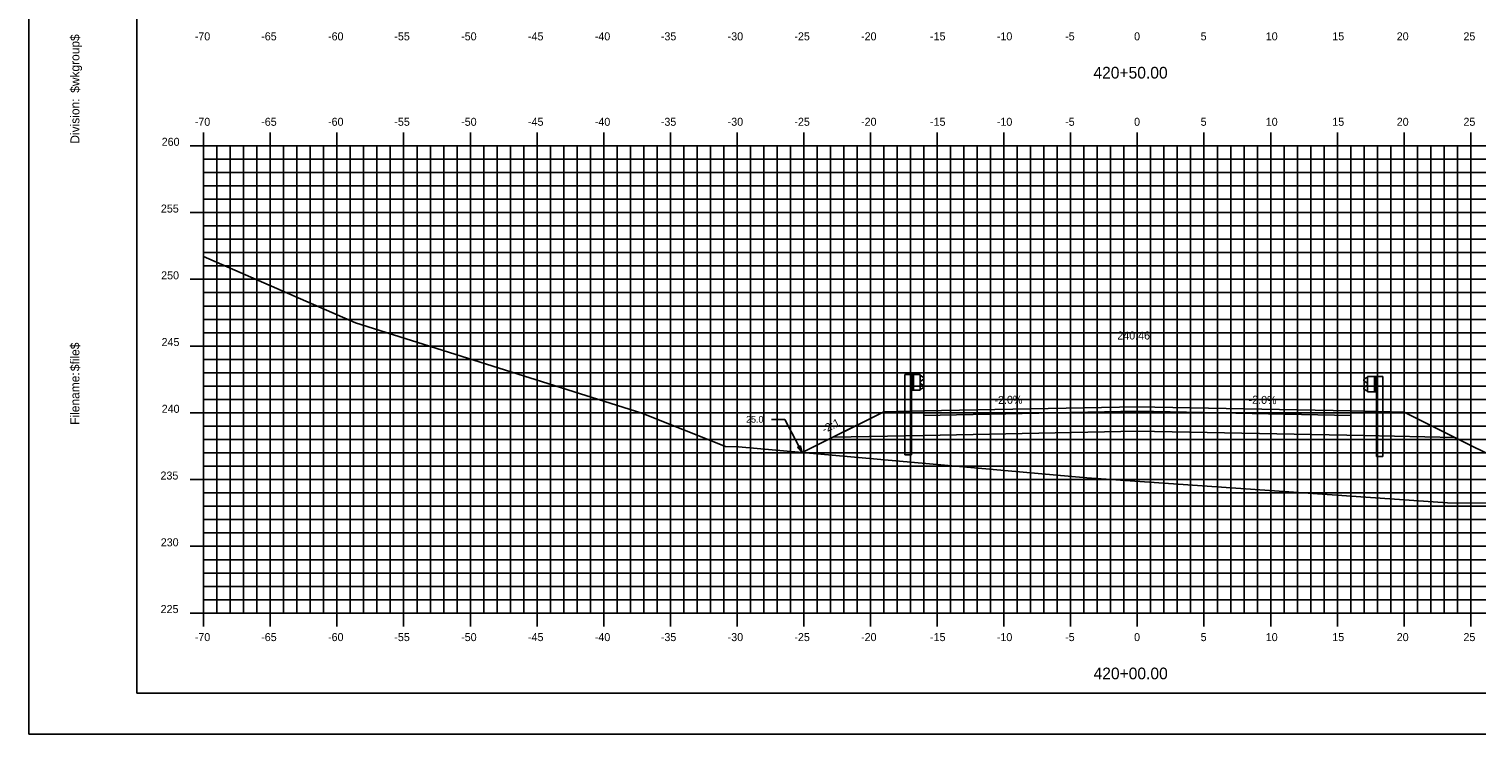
# Model space of a CAD drawing. Extents: x 1160718 to 1173142, y 616002 to 617630.
# Drawn here: x 1169435.8 to 1169544.3, y 616613.9 to 616666.7 of the extents above; entities that cross this region are included whole.
import ezdxf

# ---------------------------------------------------------------- set-up
doc = ezdxf.new("R2010")
doc.units = 0
for name, color, linetype in [('ANNOTATION', 7, 'Continuous'), ('BORDER', 7, 'Continuous'), ('D_Guardrail_Beam_Lt', 7, 'Continuous'), ('D_Guardrail_Beam_Rt', 7, 'Continuous'), ('D_Roadway_Centerline', 7, 'Continuous'), ('D_Roadway_Centerline_Text', 7, 'Continuous'), ('D_Roadway_Edge_Shoulder', 7, 'Continuous'), ('D_Roadway_Edge_TW', 7, 'Continuous'), ('D_Roadway_Pavement', 7, 'Continuous'), ('D_Roadway_SlopeLines', 7, 'Continuous'), ('D_Roadway_SubGrade', 7, 'Continuous'), ('H_V ANNOTATION', 7, 'Continuous'), ('MAJOR', 7, 'Continuous'), ('MINOR', 7, 'Continuous'), ('PLOT BOUNDARY', 7, 'Continuous'), ('S_Roadway_Centerline', 7, 'Continuous')]:
    doc.layers.add(name, color=color, linetype=linetype)

msp = doc.modelspace()

# ---------------------------------------------------------------- linework, layer by layer
at = {"layer": 'ANNOTATION'}
for p in [(1169491.45, 616637.44), (1169493.75, 616634.95)]:
    msp.add_line(p, (1169492.45, 616637.44), dxfattribs=at)
msp.add_lwpolyline([(1169496.06, 616636.1), (1169502.88, 616636.24), (1169518.88, 616636.56), (1169535.88, 616636.22), (1169542.7, 616636.08)], dxfattribs=at)
msp.add_lwpolyline([(1169493.63, 616635.45), (1169493.75, 616634.95), (1169493.41, 616635.33)], close=True, dxfattribs=at)
at = {"layer": 'BORDER'}
for p, q in [((1169443.88, 616721.93), (1169443.88, 616616.93)), ((1169443.88, 616616.93), (1169603.88, 616616.93))]:
    msp.add_line(p, q, dxfattribs=at)
at = {"layer": 'D_Guardrail_Beam_Lt'}
for p, q in [((1169501.45, 616640.79), (1169501.45, 616634.79)), ((1169501.92, 616640.79), (1169501.45, 616640.79)), ((1169502.61, 616640.79), (1169501.92, 616640.79)), ((1169501.92, 616640.79), (1169501.92, 616639.62)), ((1169501.99, 616640.79), (1169501.99, 616639.62)), ((1169502.09, 616640.79), (1169502.09, 616639.62)), ((1169502.61, 616639.62), (1169502.61, 616640.79)), ((1169502.61, 616640.7), (1169502.68, 616640.69)), ((1169502.61, 616640.24), (1169502.61, 616640.17)), ((1169502.84, 616640.44), (1169502.65, 616640.3)), ((1169502.65, 616640.1), (1169502.84, 616639.97)), ((1169502.7, 616640.68), (1169502.84, 616640.58)), ((1169501.92, 616639.62), (1169502.61, 616639.62)), ((1169501.94, 616634.79), (1169501.94, 616639.62)), ((1169502.68, 616639.72), (1169502.61, 616639.7)), ((1169502.84, 616639.82), (1169502.7, 616639.72)), ((1169501.94, 616634.79), (1169501.45, 616634.79))]:
    msp.add_line(p, q, dxfattribs=at)
for centre, major_axis, start_param, end_param in [((1169502.69, 616640.24), (-0.0789, 0), 5.323254, 6.283185), ((1169502.69, 616640.17), (-0.0789, 0), 6.283185, 7.243116), ((1169502.68, 616640.65), (0.0417, 0), 0.959931, 1.376053), ((1169502.79, 616640.51), (0.0877, 0), 5.323254, 7.243116), ((1169502.79, 616639.9), (0.0877, 0), 5.323254, 7.243116), ((1169502.68, 616639.76), (0.0417, 0), 4.907132, 5.323254)]:
    msp.add_ellipse(centre, major_axis=major_axis, ratio=0.995501, start_param=start_param, end_param=end_param, dxfattribs=at)
at = {"layer": 'D_Guardrail_Beam_Rt'}
for p, q in [((1169536.04, 616640.55), (1169535.9, 616640.45)), ((1169535.9, 616640.31), (1169536.09, 616640.17)), ((1169536.09, 616639.97), (1169535.9, 616639.84)), ((1169536.13, 616640.57), (1169536.06, 616640.56)), ((1169536.13, 616640.65), (1169536.82, 616640.65)), ((1169536.13, 616639.49), (1169536.13, 616640.65)), ((1169536.13, 616640.11), (1169536.13, 616640.04)), ((1169536.65, 616640.65), (1169536.65, 616639.49)), ((1169536.76, 616640.65), (1169536.76, 616639.49)), ((1169536.82, 616640.65), (1169537.29, 616640.65)), ((1169536.82, 616640.65), (1169536.82, 616639.49)), ((1169537.29, 616640.65), (1169537.29, 616634.65)), ((1169535.9, 616639.69), (1169536.04, 616639.59)), ((1169536.06, 616639.59), (1169536.13, 616639.57)), ((1169536.82, 616639.49), (1169536.13, 616639.49)), ((1169536.8, 616634.65), (1169536.8, 616639.49)), ((1169536.8, 616634.65), (1169537.29, 616634.65))]:
    msp.add_line(p, q, dxfattribs=at)
for centre, major_axis, start_param, end_param in [((1169535.95, 616640.38), (-0.0877, 0), 5.323254, 7.243116), ((1169536.07, 616640.52), (-0.0417, 0), 4.907132, 5.323254), ((1169536.05, 616640.11), (0.0789, 0), 0, 0.959931), ((1169536.05, 616640.04), (0.0789, 0), 5.323254, 6.283185), ((1169535.95, 616639.76), (-0.0877, 0), 5.323254, 7.243116), ((1169536.07, 616639.63), (-0.0417, 0), 0.959931, 1.376053)]:
    msp.add_ellipse(centre, major_axis=major_axis, ratio=0.995501, start_param=start_param, end_param=end_param, dxfattribs=at)
at = {"layer": 'D_Roadway_Edge_Shoulder'}
for points in [[(1169502.88, 616638.07), (1169502.88, 616637.74)], [(1169534.88, 616638.07), (1169534.88, 616637.74)]]:
    msp.add_lwpolyline(points, dxfattribs=at)
at = {"layer": 'D_Roadway_Edge_TW'}
msp.add_lwpolyline([(1169502.88, 616637.74), (1169502.88, 616638.07), (1169518.88, 616638.39), (1169534.88, 616638.07), (1169534.88, 616637.74), (1169518.88, 616638.06)], close=True, dxfattribs=at)
at = {"layer": 'D_Roadway_Pavement'}
msp.add_lwpolyline([(1169502.88, 616637.74), (1169502.88, 616637.74), (1169518.88, 616638.06), (1169534.88, 616637.74), (1169534.88, 616637.74), (1169518.88, 616638.06)], close=True, dxfattribs=at)
for points in [[(1169502.88, 616637.74), (1169502.88, 616637.74)], [(1169502.88, 616637.74), (1169502.88, 616637.74)], [(1169534.88, 616637.74), (1169534.88, 616637.74)], [(1169534.88, 616637.74), (1169534.88, 616637.74)]]:
    msp.add_lwpolyline(points, dxfattribs=at)
at = {"layer": 'D_Roadway_SlopeLines'}
for points in [[(1169499.88, 616638.01), (1169493.75, 616634.95)], [(1169538.88, 616637.99), (1169549.96, 616632.45)]]:
    msp.add_lwpolyline(points, dxfattribs=at)
at = {"layer": 'D_Roadway_SubGrade'}
for p, q in [((1169534.88, 616638.07), (1169538.88, 616637.99)), ((1169534.88, 616636.24), (1169534.88, 616638.07)), ((1169538.88, 616637.99), (1169543.74, 616635.56))]:
    msp.add_line(p, q, dxfattribs=at)
for points in [[(1169502.88, 616636.24), (1169502.88, 616638.07), (1169499.88, 616638.01), (1169496.06, 616636.1)], [(1169502.88, 616636.24), (1169502.88, 616637.74), (1169518.88, 616638.06), (1169534.88, 616637.74), (1169534.88, 616636.24)]]:
    msp.add_lwpolyline(points, dxfattribs=at)
at = {"layer": 'MAJOR'}
for p, q in [((1169448.88, 616658.93), (1169448.88, 616657.93)), ((1169453.88, 616658.93), (1169453.88, 616657.93)), ((1169458.88, 616658.93), (1169458.88, 616657.93)), ((1169463.88, 616658.93), (1169463.88, 616657.93)), ((1169468.88, 616658.93), (1169468.88, 616657.93)), ((1169473.88, 616658.93), (1169473.88, 616657.93)), ((1169478.88, 616658.93), (1169478.88, 616657.93)), ((1169483.88, 616658.93), (1169483.88, 616657.93)), ((1169488.88, 616658.93), (1169488.88, 616657.93)), ((1169493.88, 616658.93), (1169493.88, 616657.93)), ((1169498.88, 616658.93), (1169498.88, 616657.93)), ((1169503.88, 616658.93), (1169503.88, 616657.93)), ((1169508.88, 616658.93), (1169508.88, 616657.93)), ((1169513.88, 616658.93), (1169513.88, 616657.93)), ((1169518.88, 616658.93), (1169518.88, 616657.93)), ((1169523.88, 616658.93), (1169523.88, 616657.93)), ((1169528.88, 616658.93), (1169528.88, 616657.93)), ((1169533.88, 616658.93), (1169533.88, 616657.93)), ((1169538.88, 616658.93), (1169538.88, 616657.93)), ((1169543.88, 616658.93), (1169543.88, 616657.93)), ((1169447.88, 616657.93), (1169448.88, 616657.93)), ((1169448.88, 616657.93), (1169588.88, 616657.93)), ((1169448.88, 616622.93), (1169448.88, 616657.93)), ((1169448.88, 616622.93), (1169448.88, 616657.93)), ((1169448.88, 616657.93), (1169588.88, 616657.93)), ((1169453.88, 616622.93), (1169453.88, 616657.93)), ((1169458.88, 616622.93), (1169458.88, 616657.93)), ((1169463.88, 616622.93), (1169463.88, 616657.93)), ((1169468.88, 616622.93), (1169468.88, 616657.93)), ((1169473.88, 616622.93), (1169473.88, 616657.93)), ((1169478.88, 616622.93), (1169478.88, 616657.93)), ((1169483.88, 616622.93), (1169483.88, 616657.93)), ((1169488.88, 616622.93), (1169488.88, 616657.93)), ((1169493.88, 616622.93), (1169493.88, 616657.93)), ((1169498.88, 616622.93), (1169498.88, 616657.93)), ((1169503.88, 616622.93), (1169503.88, 616657.93)), ((1169508.88, 616622.93), (1169508.88, 616657.93)), ((1169513.88, 616622.93), (1169513.88, 616657.93)), ((1169518.88, 616622.93), (1169518.88, 616657.93)), ((1169523.88, 616622.93), (1169523.88, 616657.93)), ((1169528.88, 616622.93), (1169528.88, 616657.93)), ((1169533.88, 616622.93), (1169533.88, 616657.93)), ((1169538.88, 616622.93), (1169538.88, 616657.93)), ((1169543.88, 616622.93), (1169543.88, 616657.93)), ((1169447.88, 616652.93), (1169448.88, 616652.93)), ((1169448.88, 616652.93), (1169588.88, 616652.93)), ((1169447.88, 616647.93), (1169448.88, 616647.93)), ((1169448.88, 616647.93), (1169588.88, 616647.93)), ((1169447.88, 616642.93), (1169448.88, 616642.93)), ((1169448.88, 616642.93), (1169588.88, 616642.93)), ((1169447.88, 616637.93), (1169448.88, 616637.93)), ((1169448.88, 616637.93), (1169588.88, 616637.93)), ((1169447.88, 616632.93), (1169448.88, 616632.93)), ((1169448.88, 616632.93), (1169588.88, 616632.93)), ((1169447.88, 616627.93), (1169448.88, 616627.93)), ((1169448.88, 616627.93), (1169588.88, 616627.93)), ((1169447.88, 616622.93), (1169448.88, 616622.93)), ((1169448.88, 616622.93), (1169588.88, 616622.93)), ((1169448.88, 616622.93), (1169588.88, 616622.93)), ((1169448.88, 616621.93), (1169448.88, 616622.93)), ((1169453.88, 616621.93), (1169453.88, 616622.93)), ((1169458.88, 616621.93), (1169458.88, 616622.93)), ((1169463.88, 616621.93), (1169463.88, 616622.93)), ((1169468.88, 616621.93), (1169468.88, 616622.93)), ((1169473.88, 616621.93), (1169473.88, 616622.93)), ((1169478.88, 616621.93), (1169478.88, 616622.93)), ((1169483.88, 616621.93), (1169483.88, 616622.93)), ((1169488.88, 616621.93), (1169488.88, 616622.93)), ((1169493.88, 616621.93), (1169493.88, 616622.93)), ((1169498.88, 616621.93), (1169498.88, 616622.93)), ((1169503.88, 616621.93), (1169503.88, 616622.93)), ((1169508.88, 616621.93), (1169508.88, 616622.93)), ((1169513.88, 616621.93), (1169513.88, 616622.93)), ((1169518.88, 616621.93), (1169518.88, 616622.93)), ((1169523.88, 616621.93), (1169523.88, 616622.93)), ((1169528.88, 616621.93), (1169528.88, 616622.93)), ((1169533.88, 616621.93), (1169533.88, 616622.93)), ((1169538.88, 616621.93), (1169538.88, 616622.93)), ((1169543.88, 616621.93), (1169543.88, 616622.93))]:
    msp.add_line(p, q, dxfattribs=at)
at = {"layer": 'MINOR'}
for p, q in [((1169449.88, 616622.93), (1169449.88, 616657.93)), ((1169450.88, 616622.93), (1169450.88, 616657.93)), ((1169451.88, 616622.93), (1169451.88, 616657.93)), ((1169452.88, 616622.93), (1169452.88, 616657.93)), ((1169454.88, 616622.93), (1169454.88, 616657.93)), ((1169455.88, 616622.93), (1169455.88, 616657.93)), ((1169456.88, 616622.93), (1169456.88, 616657.93)), ((1169457.88, 616622.93), (1169457.88, 616657.93)), ((1169459.88, 616622.93), (1169459.88, 616657.93)), ((1169460.88, 616622.93), (1169460.88, 616657.93)), ((1169461.88, 616622.93), (1169461.88, 616657.93)), ((1169462.88, 616622.93), (1169462.88, 616657.93)), ((1169464.88, 616622.93), (1169464.88, 616657.93)), ((1169465.88, 616622.93), (1169465.88, 616657.93)), ((1169466.88, 616622.93), (1169466.88, 616657.93)), ((1169467.88, 616622.93), (1169467.88, 616657.93)), ((1169469.88, 616622.93), (1169469.88, 616657.93)), ((1169470.88, 616622.93), (1169470.88, 616657.93)), ((1169471.88, 616622.93), (1169471.88, 616657.93)), ((1169472.88, 616622.93), (1169472.88, 616657.93)), ((1169474.88, 616622.93), (1169474.88, 616657.93)), ((1169475.88, 616622.93), (1169475.88, 616657.93)), ((1169476.88, 616622.93), (1169476.88, 616657.93)), ((1169477.88, 616622.93), (1169477.88, 616657.93)), ((1169479.88, 616622.93), (1169479.88, 616657.93)), ((1169480.88, 616622.93), (1169480.88, 616657.93)), ((1169481.88, 616622.93), (1169481.88, 616657.93)), ((1169482.88, 616622.93), (1169482.88, 616657.93)), ((1169484.88, 616622.93), (1169484.88, 616657.93)), ((1169485.88, 616622.93), (1169485.88, 616657.93)), ((1169486.88, 616622.93), (1169486.88, 616657.93)), ((1169487.88, 616622.93), (1169487.88, 616657.93)), ((1169489.88, 616622.93), (1169489.88, 616657.93)), ((1169490.88, 616622.93), (1169490.88, 616657.93)), ((1169491.88, 616622.93), (1169491.88, 616657.93)), ((1169492.88, 616622.93), (1169492.88, 616657.93)), ((1169494.88, 616622.93), (1169494.88, 616657.93)), ((1169495.88, 616622.93), (1169495.88, 616657.93)), ((1169496.88, 616622.93), (1169496.88, 616657.93)), ((1169497.88, 616622.93), (1169497.88, 616657.93)), ((1169499.88, 616622.93), (1169499.88, 616657.93)), ((1169500.88, 616622.93), (1169500.88, 616657.93)), ((1169501.88, 616622.93), (1169501.88, 616657.93)), ((1169502.88, 616622.93), (1169502.88, 616657.93)), ((1169504.88, 616622.93), (1169504.88, 616657.93)), ((1169505.88, 616622.93), (1169505.88, 616657.93)), ((1169506.88, 616622.93), (1169506.88, 616657.93)), ((1169507.88, 616622.93), (1169507.88, 616657.93)), ((1169509.88, 616622.93), (1169509.88, 616657.93)), ((1169510.88, 616622.93), (1169510.88, 616657.93)), ((1169511.88, 616622.93), (1169511.88, 616657.93)), ((1169512.88, 616622.93), (1169512.88, 616657.93)), ((1169514.88, 616622.93), (1169514.88, 616657.93)), ((1169515.88, 616622.93), (1169515.88, 616657.93)), ((1169516.88, 616622.93), (1169516.88, 616657.93)), ((1169517.88, 616622.93), (1169517.88, 616657.93)), ((1169519.88, 616622.93), (1169519.88, 616657.93)), ((1169520.88, 616622.93), (1169520.88, 616657.93)), ((1169521.88, 616622.93), (1169521.88, 616657.93)), ((1169522.88, 616622.93), (1169522.88, 616657.93)), ((1169524.88, 616622.93), (1169524.88, 616657.93)), ((1169525.88, 616622.93), (1169525.88, 616657.93)), ((1169526.88, 616622.93), (1169526.88, 616657.93)), ((1169527.88, 616622.93), (1169527.88, 616657.93)), ((1169529.88, 616622.93), (1169529.88, 616657.93)), ((1169530.88, 616622.93), (1169530.88, 616657.93)), ((1169531.88, 616622.93), (1169531.88, 616657.93)), ((1169532.88, 616622.93), (1169532.88, 616657.93)), ((1169534.88, 616622.93), (1169534.88, 616657.93)), ((1169535.88, 616622.93), (1169535.88, 616657.93)), ((1169536.88, 616622.93), (1169536.88, 616657.93)), ((1169537.88, 616622.93), (1169537.88, 616657.93)), ((1169539.88, 616622.93), (1169539.88, 616657.93)), ((1169540.88, 616622.93), (1169540.88, 616657.93)), ((1169541.88, 616622.93), (1169541.88, 616657.93)), ((1169542.88, 616622.93), (1169542.88, 616657.93)), ((1169448.88, 616656.93), (1169588.88, 616656.93)), ((1169448.88, 616656.93), (1169449.88, 616656.93)), ((1169448.88, 616655.93), (1169588.88, 616655.93)), ((1169448.88, 616655.93), (1169449.88, 616655.93)), ((1169448.88, 616654.93), (1169588.88, 616654.93)), ((1169448.88, 616654.93), (1169449.88, 616654.93)), ((1169448.88, 616653.93), (1169588.88, 616653.93)), ((1169448.88, 616653.93), (1169449.88, 616653.93)), ((1169448.88, 616651.93), (1169588.88, 616651.93)), ((1169448.88, 616651.93), (1169449.88, 616651.93)), ((1169448.88, 616650.93), (1169588.88, 616650.93)), ((1169448.88, 616650.93), (1169449.88, 616650.93)), ((1169448.88, 616649.93), (1169588.88, 616649.93)), ((1169448.88, 616649.93), (1169449.88, 616649.93)), ((1169448.88, 616648.93), (1169588.88, 616648.93)), ((1169448.88, 616648.93), (1169449.88, 616648.93)), ((1169448.88, 616646.93), (1169588.88, 616646.93)), ((1169448.88, 616646.93), (1169449.88, 616646.93)), ((1169448.88, 616645.93), (1169588.88, 616645.93)), ((1169448.88, 616645.93), (1169449.88, 616645.93)), ((1169448.88, 616644.93), (1169588.88, 616644.93)), ((1169448.88, 616644.93), (1169449.88, 616644.93)), ((1169448.88, 616643.93), (1169588.88, 616643.93)), ((1169448.88, 616643.93), (1169449.88, 616643.93)), ((1169448.88, 616641.93), (1169588.88, 616641.93)), ((1169448.88, 616641.93), (1169449.88, 616641.93)), ((1169448.88, 616640.93), (1169588.88, 616640.93)), ((1169448.88, 616640.93), (1169449.88, 616640.93)), ((1169448.88, 616639.93), (1169588.88, 616639.93)), ((1169448.88, 616639.93), (1169449.88, 616639.93)), ((1169448.88, 616638.93), (1169588.88, 616638.93)), ((1169448.88, 616638.93), (1169449.88, 616638.93)), ((1169448.88, 616636.93), (1169588.88, 616636.93)), ((1169448.88, 616636.93), (1169449.88, 616636.93)), ((1169448.88, 616635.93), (1169588.88, 616635.93)), ((1169448.88, 616635.93), (1169449.88, 616635.93)), ((1169448.88, 616634.93), (1169588.88, 616634.93)), ((1169448.88, 616634.93), (1169449.88, 616634.93)), ((1169448.88, 616633.93), (1169588.88, 616633.93)), ((1169448.88, 616633.93), (1169449.88, 616633.93)), ((1169448.88, 616631.93), (1169588.88, 616631.93)), ((1169448.88, 616631.93), (1169449.88, 616631.93)), ((1169448.88, 616630.93), (1169588.88, 616630.93)), ((1169448.88, 616630.93), (1169449.88, 616630.93)), ((1169448.88, 616629.93), (1169588.88, 616629.93)), ((1169448.88, 616629.93), (1169449.88, 616629.93)), ((1169448.88, 616628.93), (1169588.88, 616628.93)), ((1169448.88, 616628.93), (1169449.88, 616628.93)), ((1169448.88, 616626.93), (1169588.88, 616626.93)), ((1169448.88, 616626.93), (1169449.88, 616626.93)), ((1169448.88, 616625.93), (1169588.88, 616625.93)), ((1169448.88, 616625.93), (1169449.88, 616625.93)), ((1169448.88, 616624.93), (1169588.88, 616624.93)), ((1169448.88, 616624.93), (1169449.88, 616624.93)), ((1169448.88, 616623.93), (1169588.88, 616623.93)), ((1169448.88, 616623.93), (1169449.88, 616623.93))]:
    msp.add_line(p, q, dxfattribs=at)
at = {"layer": 'PLOT BOUNDARY'}
msp.add_lwpolyline([(1169435.79, 616613.87), (1169605.79, 616613.87), (1169605.79, 616723.87), (1169435.79, 616723.87)], close=True, dxfattribs=at)
at = {"layer": 'S_Roadway_Centerline'}
msp.add_lwpolyline([(1169448.88, 616649.65), (1169460.28, 616644.68), (1169481.74, 616637.9), (1169488.02, 616635.4), (1169488.97, 616635.37), (1169515.09, 616633.05), (1169542.13, 616631.19), (1169551.75, 616631.17), (1169573.15, 616631.39), (1169584.94, 616635.13), (1169588.88, 616635.84)], dxfattribs=at)

# ---------------------------------------------------------------- texts
at = {"layer": 'ANNOTATION'}
for s, rotation, p in [('-2.0%', 1.1458, (1169508.18, 616638.58)), ('-2.0%', 358.8542, (1169527.22, 616638.62)), ('-2:1', 26.5651, (1169495.42, 616636.38))]:
    msp.add_text(s, height=0.6, rotation=rotation, dxfattribs=at).set_placement(p)
msp.add_text("25.0'", height=0.5, dxfattribs=at).set_placement((1169489.55, 616637.19))
at = {"layer": 'BORDER'}
for s, p in [('$wkgroup$', (1169439.57, 616661.9)), ('Division:', (1169439.57, 616658.09)), ('$file$', (1169439.57, 616641.05)), ('Filename:', (1169439.57, 616637.03))]:
    msp.add_text(s, height=0.67, rotation=90, dxfattribs=at).set_placement(p)
at = {"layer": 'D_Roadway_Centerline'}
for s, p in [('C', (1169518.88, 616638.39)), ('L', (1169518.88, 616638.38))]:
    msp.add_text(s, height=0.0146, dxfattribs=at).set_placement(p)
at = {"layer": 'D_Roadway_Centerline_Text'}
msp.add_text('240.46', height=0.6, dxfattribs=at).set_placement((1169517.38, 616643.42))
at = {"layer": 'H_V ANNOTATION'}
for s, height, p in [('-70', 0.6, (1169448.22, 616665.83)), ('-65', 0.6, (1169453.2, 616665.83)), ('-60', 0.6, (1169458.21, 616665.83)), ('-55', 0.6, (1169463.18, 616665.83)), ('-50', 0.6, (1169468.19, 616665.83)), ('-45', 0.6, (1169473.2, 616665.83)), ('-40', 0.6, (1169478.21, 616665.83)), ('-35', 0.6, (1169483.16, 616665.83)), ('-30', 0.6, (1169488.17, 616665.83)), ('-25', 0.6, (1169493.17, 616665.83)), ('-20', 0.6, (1169498.17, 616665.83)), ('-15', 0.6, (1169503.34, 616665.83)), ('-10', 0.6, (1169508.35, 616665.83)), ('-5', 0.6, (1169513.47, 616665.83)), ('0', 0.6, (1169518.64, 616665.83)), ('5', 0.6, (1169523.63, 616665.83)), ('10', 0.6, (1169528.51, 616665.83)), ('15', 0.6, (1169533.5, 616665.83)), ('20', 0.6, (1169538.33, 616665.83)), ('25', 0.6, (1169543.33, 616665.83)), ('420+50.00', 0.875, (1169515.59, 616662.97)), ('-70', 0.6, (1169448.22, 616659.43)), ('-65', 0.6, (1169453.2, 616659.43)), ('-60', 0.6, (1169458.21, 616659.43)), ('-55', 0.6, (1169463.18, 616659.43)), ('-50', 0.6, (1169468.19, 616659.43)), ('-45', 0.6, (1169473.2, 616659.43)), ('-40', 0.6, (1169478.21, 616659.43)), ('-35', 0.6, (1169483.16, 616659.43)), ('-30', 0.6, (1169488.17, 616659.43)), ('-25', 0.6, (1169493.17, 616659.43)), ('-20', 0.6, (1169498.17, 616659.43)), ('-15', 0.6, (1169503.34, 616659.43)), ('-10', 0.6, (1169508.35, 616659.43)), ('-5', 0.6, (1169513.47, 616659.43)), ('0', 0.6, (1169518.64, 616659.43)), ('5', 0.6, (1169523.63, 616659.43)), ('10', 0.6, (1169528.51, 616659.43)), ('15', 0.6, (1169533.5, 616659.43)), ('20', 0.6, (1169538.33, 616659.43)), ('25', 0.6, (1169543.33, 616659.43)), ('260', 0.6, (1169445.74, 616657.93)), ('255', 0.6, (1169445.68, 616652.93)), ('250', 0.6, (1169445.7, 616647.93)), ('245', 0.6, (1169445.73, 616642.93)), ('240', 0.6, (1169445.74, 616637.93)), ('235', 0.6, (1169445.65, 616632.93)), ('230', 0.6, (1169445.67, 616627.93)), ('225', 0.6, (1169445.66, 616622.93)), ('-70', 0.6, (1169448.22, 616620.83)), ('-65', 0.6, (1169453.2, 616620.83)), ('-60', 0.6, (1169458.21, 616620.83)), ('-55', 0.6, (1169463.18, 616620.83)), ('-50', 0.6, (1169468.19, 616620.83)), ('-45', 0.6, (1169473.2, 616620.83)), ('-40', 0.6, (1169478.21, 616620.83)), ('-35', 0.6, (1169483.16, 616620.83)), ('-30', 0.6, (1169488.17, 616620.83)), ('-25', 0.6, (1169493.17, 616620.83)), ('-20', 0.6, (1169498.17, 616620.83)), ('-15', 0.6, (1169503.34, 616620.83)), ('-10', 0.6, (1169508.35, 616620.83)), ('-5', 0.6, (1169513.47, 616620.83)), ('0', 0.6, (1169518.64, 616620.83)), ('5', 0.6, (1169523.63, 616620.83)), ('10', 0.6, (1169528.51, 616620.83)), ('15', 0.6, (1169533.5, 616620.83)), ('20', 0.6, (1169538.33, 616620.83)), ('25', 0.6, (1169543.33, 616620.83)), ('420+00.00', 0.875, (1169515.6, 616617.97))]:
    msp.add_text(s, height=height, dxfattribs=at).set_placement(p)

doc.saveas('drawing.dxf')
